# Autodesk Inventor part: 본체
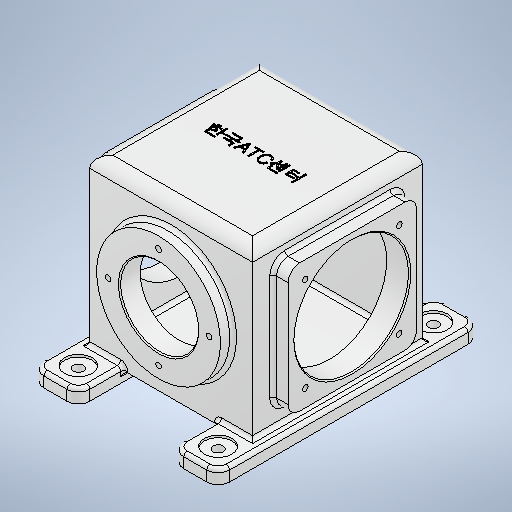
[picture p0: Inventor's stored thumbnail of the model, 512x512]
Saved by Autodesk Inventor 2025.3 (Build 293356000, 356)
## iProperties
Created: 2026-01
Part Number: 본체
Material: 알루미늄 6061
Document SubType Name: Modeling
Designer: PC01-12
Density: 2.7 g/cm^3
Appearance: 알루미늄 - 평지
Mass: 2756.19 g
Surface Area: 2492.21 cm^2
Volume: 1020.81 cm^3
Author: PC01-12
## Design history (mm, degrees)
sketch "스케치1"
  geometry: L1 (-71, -74)-(71, -74); L2 (71, -74)-(71, 74); L3 (71, 74)-(-71, 74); L4 (-71, 74)-(-71, -74); L5 (-71, -74)-(71, 74); L6 (71, -74)-(-71, 74); 1 further point
  constraints: 12 end point, 2 midpoint, 2 parallel, 1 horizontal, 1 perpendicular
  dimensions: "d0" = 142 distance of L3.end L2.end; "d1" = 148 distance of L2.end L1.end
extrude "돌출1" new body sketch "스케치1" stored distance "d2" = 148; taper "d3" = 0 deg
sketch "스케치2"
  geometry: C1 r 54 at (0, 0); 1 further point
  constraints: 1 centre point, 1 coincident
  dimensions: "d4" = 108 diameter of C1
extrude "돌출2" join sketch "스케치2" distance "d5" = 11; taper "d6" = 0 deg
sketch "스케치3"
  geometry: C1 r 34 at (0, 0); 1 further point
  constraints: 1 centre point, 1 coincident
  dimensions: "d7" = 68 diameter of C1
extrude "돌출3" cut sketch "스케치3" distance "d8" = 50; taper "d9" = 0 deg
sketch "스케치4" dims "d10" = 88
  geometry: 3 further points
  constraints: 2 vertical alignment, 1 coincident, 2 other
hole "구멍1" sketch "스케치4" at (0, 44) diameter "d11" = 4.917; stored, may be unused: countersink angle "d15" = 90 deg, drill point angle "d17" = 118 deg; dims "d12" = 12, "d13" = 4, "d14" = 2, "d16" = 14
sketch "스케치5"
  geometry: L1 (148, 148)-(0, 148) reference; L2 (0, 0)-(0, 148) reference; L3 (0, 0)-(148, 0) reference; L4 (148, 148)-(148, 0) reference; L5 (18, 130)-(130, 130); L6 (130, 130)-(130, 18); L7 (130, 18)-(18, 18); L8 (18, 18)-(18, 130); 1 further point
  constraints: 8 end point, 3 other
  dimensions: "d43" = 112 distance of L5.start L5.end
extrude "돌출4" join sketch "스케치5" distance "d22" = 13; taper "d23" = 0 deg
sketch "스케치6"
  geometry: C1 r 50 at (74, 74); 1 further point
  constraints: 1 centre point, 1 coincident
  dimensions: "d24" = 100 diameter of C1
extrude "돌출5" cut sketch "스케치6" stored distance "d25" = 148; taper "d26" = 0 deg
sketch "스케치7"
  geometry: L1 (18, 18)-(130, 18) reference; L2 (130, 18)-(130, 130) reference; L3 (130, 130)-(18, 130) reference; L4 (18, 130)-(18, 18) reference; L5 (33, 115)-(115, 115); L6 (115, 115)-(115, 33); L7 (115, 33)-(33, 33); L8 (33, 33)-(33, 115); C1 r 50 at (74, 74) reference; 5 further points
  constraints: 8 end point, 4 coincident, 3 other
  dimensions: "d44" = 82 distance of L5.start L5.end
hole "구멍2" sketch "스케치7" at (33, 115), (115, 115), (115, 33), (33, 33) diameter "d28" = 4.917; stored, may be unused: countersink angle "d32" = 90 deg, drill point angle "d34" = 118 deg; dims "d29" = 12, "d30" = 4, "d31" = 2, "d33" = 14
node "작업 평면1"
sketch "스케치8"
  geometry: L1 (-41, 114)-(-81, 114); L2 (-81, 114)-(-81, -114); L3 (-81, -114)-(-41, -114); L4 (-41, -114)-(-41, 114); L5 (81, 114)-(41, 114); L6 (41, 114)-(41, -114); L7 (41, -114)-(81, -114); L8 (81, -114)-(81, 114); L9 (0, -105.8)-(0, 116.8) reference; L10 (117.6, 0)-(-117.6, 0) reference; 1 further point
  constraints: 16 end point, 4 parallel, 2 horizontal, 2 perpendicular, 3 other
  dimensions: "d36" = 162 distance between parallel lines of L2 L8; "d37" = 40 distance between parallel lines of L6 L8; "d38" = 40 distance between parallel lines of L2 L4; "d39" = 228 distance between parallel lines of L1 L3; "d40" = 228 distance between parallel lines of L7 L5
extrude "돌출6" join sketch "스케치8" distance "d41" = 12; taper "d42" = 0 deg
sketch "스케치9"
  geometry: L1 (-61, -94)-(61, -94); L2 (61, -94)-(61, 94); L3 (61, 94)-(-61, 94); L4 (-61, 94)-(-61, -94); L5 (-61, -94)-(61, 94); L6 (61, -94)-(-61, 94); C1 r 12 at (-61, 94); C2 r 12 at (61, 94); C3 r 12 at (61, -94); C4 r 12 at (-61, -94); 1 further point
  constraints: 12 end point, 4 centre point, 4 coincident, 2 midpoint, 2 parallel, 1 horizontal, 1 perpendicular
  dimensions: "d46" = 122 distance of L3.end L2.end; "d47" = 188 distance of L2.end L1.end; "d48" = 24 diameter of C1; "d49" = 24 diameter of C2; "d50" = 24 diameter of C3; "d51" = 24 diameter of C4
extrude "돌출7" cut sketch "스케치9" distance "d52" = 2; taper "d53" = 0 deg
sketch "스케치10"
  geometry: L1 (0, -188)-(122, -188); L2 (122, -188)-(122, 0); L3 (122, 0)-(0, 0); L4 (0, 0)-(0, -188); L5 (0, -188)-(122, 0); L6 (122, -188)-(0, 0); C1 r 4.5 at (0, 0); C2 r 4.5 at (122, 0); C3 r 4.5 at (122, -188); C4 r 4.5 at (0, -188); 1 further point
  constraints: 12 end point, 4 centre point, 4 coincident, 2 midpoint, 2 parallel, 1 horizontal, 1 perpendicular
  dimensions: "d54" = 122 distance of L3.end L2.end; "d55" = 188 distance of L2.end L1.end; "d56" = 9 diameter of C1; "d57" = 9 diameter of C2; "d58" = 9 diameter of C3; "d59" = 9 diameter of C4
extrude "돌출8" cut sketch "스케치10" distance "d60" = 10; taper "d61" = 0 deg
fillet "모깎기2" dims "d62" = 3
fillet "모깎기3" dims "d63" = 10
chamfer "모따기1" distance "d65" = 1; stored, may be unused: second distance "d66" = 2, angle "d67" = 45 deg
fillet "모깎기5" dims "d68" = 10
fillet "모깎기6" dims "d69" = 3
fillet "모깎기7" dims "d70" = 3
fillet "모깎기8" dims "d71" = 10
sketch "스케치11"
  geometry: L1 (19.247, -58.543)-(102.205, -58.543); L2 (102.205, -58.543)-(102.205, -70.551); L3 (102.205, -70.551)-(19.247, -70.551); L4 (19.247, -70.551)-(19.247, -58.543); 1 further point
  constraints: 2 other
feature "엠보싱1" sketch "스케치11" dims "d0" = 142, "d1" = 148, "d72" = 0.5, "d73" = 0
sketch "스케치12"
  geometry: L1 (61, -67)-(-61, -67); L2 (-64, -64)-(-64, 64); L3 (-61, 67)-(61, 67); L4 (64, 64)-(64, -64); L5 (64, -67)-(-64, 67); L6 (-64, -67)-(64, 67); A1 r 3 centre (-61, -64) between (-64, -64) and (-61, -67); A2 r 3 centre (61, -64) between (61, -67) and (64, -64); A3 r 3 centre (61, 64) between (64, 64) and (61, 67); A4 r 3 centre (-61, 64) between (-61, 67) and (-64, 64); 1 further point
  constraints: 12 end point, 8 point on circle, 8 point on line, 8 tangent, 4 centre point, 2 midpoint, 2 parallel, 1 horizontal, 1 perpendicular
  dimensions: "d74" = 128 distance of L5.end L6.end; "d75" = 134 distance of L6.start L5.end; "d78" = 3 radius of A1; "d79" = 3 radius of A2; "d80" = 3 radius of A3 (derived); "d81" = 3 radius of A4 (derived)
extrude "돌출9" cut sketch "스케치12" stored distance "d76" = 134; taper "d77" = 0 deg
fillet "모깎기9" dims "d82" = 3
node "솔리드1"
pattern_circular "원형 패턴1" dims angle "d19" = 360 deg
mirror "미러1"
mirror "미러2"
node "투영된 루프1"
node "투영된 루프2"
feature "A9D066F2-1C7D-4E18-AEED-F7BC21143FA4" dims "d28" = 4.917, "d29" = 12, "d30" = 4, "d31" = 2, "d32" = 90 deg, "d33" = 14, "d34" = 118 deg
other parameters: "d35" = -82
